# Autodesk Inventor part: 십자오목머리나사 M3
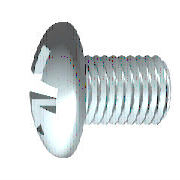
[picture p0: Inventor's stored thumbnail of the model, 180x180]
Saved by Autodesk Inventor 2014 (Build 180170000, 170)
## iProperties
Created: 2012-02
Part Number: 십자오목머리나사 M3
Material: 강철, 연강
Description: 십자 오목 머리 나사
Document SubType Name: Modeling
Standard: KS B 1023
Designer: mduedu
Standards Organization: KS
Language: ko-KR
Size Designation: A  M 3 x 6 - H
Categories: <MemberInstance><Categories><Category DisplayName="조임쇠" InternalName="e4da775c-781d-43d5-af7c-5136215cf5a6" Mnemonic="FSTN"><Category DisplayName="볼트" InternalN
Density: 7.86 g/cm^3
Appearance: 강철
Mass: 0.662382 g
Surface Area: 1.40192 cm^2
Volume: 0.0842726 cm^3
IsCustomPart: 0
Author: mduedu
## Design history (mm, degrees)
body "Solid1"
workplane "Work Plane3"
sketch "스케치2"
  geometry: L1 (-3.72, 0)-(3.72, 0) reference; L2 (0, -3.72)-(0, 3.72) reference; L3 (0, 1.5)-(0, 0); L4 (0, 0)-(1.5, 0); L5 (0, 0)-(1.879, 1.879); L6 (0.253, 1.479)-(0.261, 0.456); L7 (1.479, 0.253)-(0.456, 0.261); L8 (0.253, -1.479)-(0.261, -0.456); L9 (1.479, -0.253)-(0.456, -0.261); L10 (-0.253, 1.479)-(-0.261, 0.456); L11 (-1.479, 0.253)-(-0.456, 0.261); L12 (-1.479, -0.253)-(-0.456, -0.261); L13 (-0.253, -1.479)-(-0.261, -0.456); A1 r 0.45 centre (0, 0) between (0.45, 0) and (0, 0.45); A2 r 1.5 centre (0, 0) between (1.5, 0) and (1.479, 0.253); A3 r 1.5 centre (0, 0) between (0.253, 1.479) and (0, 1.5); A4 r 1.5 centre (0, 0) between (1.479, 0.253) and (0.253, 1.479); A5 r 1.5 centre (0, 0) between (0, -1.5) and (0.253, -1.479); A6 r 1.5 centre (0, 0) between (0.253, -1.479) and (1.479, -0.253); A7 r 1.5 centre (0, 0) between (1.479, -0.253) and (1.5, 0); A8 r 1.5 centre (0, 0) between (-1.479, 0.253) and (-1.5, 0); A9 r 1.5 centre (0, 0) between (-0.253, 1.479) and (-1.479, 0.253); A10 r 1.5 centre (0, 0) between (0, 1.5) and (-0.253, 1.479); A11 r 1.5 centre (0, 0) between (-1.5, 0) and (-1.479, -0.253); A12 r 1.5 centre (0, 0) between (-1.479, -0.253) and (-0.253, -1.479); A13 r 1.5 centre (0, 0) between (-0.253, -1.479) and (0, -1.5); A14 r 0.525 centre (0, 0) between (0.525, 0) and (0, 0.525); A15 r 0.197 centre (0.457, 0.457) between (0.261, 0.456) and (0.456, 0.261); A16 r 0.197 centre (0.457, -0.457) between (0.456, -0.261) and (0.261, -0.456); A17 r 0.197 centre (-0.457, 0.457) between (-0.456, 0.261) and (-0.261, 0.456); A18 r 0.197 centre (-0.457, -0.457) between (-0.261, -0.456) and (-0.456, -0.261); 1 further point
  constraints: 38 point on circle, 22 end point, 19 symmetric about line, 18 centre point, 4 coincident, 3 collinear, 3 point on line, 3 tangent, 1 perpendicular, 21 other
  dimensions: "d4" = 45 deg angle of L5 L4; "d5" = 0.9 diameter of A1 (= 0.3 x SDM); "d6" = 3 diameter of A4 (= SDM); "d7" = 0.2525 distance from line of L6.start L3 (= 0.5 x SBR); "d14" = 1.05 diameter of A14 (= 0.35 x SDM)
extrude "슬롯" join sketch "스케치2" taper "d15" = 5 deg; stored distance "d54" = 10
revolve "절단부" stored, may be unused: angle "d56" = 90 deg
revolve "본체" stored, may be unused: angle "d18" = 90 deg
workplane "Work Plane1"
sketch "스케치1"
  geometry: L1 (6, 0)-(6, 1.5); L2 (6, 1.5)-(1, 1.5); L3 (3.962, 5.08)-(3.962, 5.08); L4 (-2.4, 0)-(-2.4, 2.59); L5 (-2.2, 1.4)-(-1.036, 0.82); L6 (-1.036, 0.82)-(-0.6, 0); L7 (-0.6, 0)-(6, 0); L8 (-4.305, 0)-(7.717, 0) reference; L9 (0, -1.016)-(0, 6.096) reference; L10 (-2.2, 1.4)-(-2.4, 1.5); L11 (-1.636, 2.657)-(-2.4, 2.59); L12 (-1.636, 2.657)-(0, 2.8); L13 (0, 2.8)-(0, 1.347); L14 (0, 1.347)-(0.693, 1.347); L15 (0.693, 1.347)-(1, 1.5); L16 (1, 1.5)-(0, 1.5); A1 r 5 centre (2.6, 0) between (-1.636, 2.657) and (-2.4, 0)
  constraints: 28 end point, 5 point on line, 4 collinear, 4 point on circle, 3 parallel, 2 perpendicular, 1 centre point, 1 horizontal, 1 tangent
  dimensions: "d1" = 3 diameter of L2 L7 (= GD); "d2" = 1.8 distance from line of L6.end L4 (= STI); "d11" = 3 diameter of L10.end L7 (= SDM); "d12" = 62 deg angle of L6 L7; "d13" = 26.5 deg angle of L5 L7; "d17" = 5.6 diameter of L12.end L7 (= KOD); "d19" = 5 deg angle of L12 L7 (= KEWI); "d20" = 2.4 distance between parallel lines of L4 L13 (= KOH); "d21" = 5 radius of A1 (= KR); "d23" = 2.6935 diameter of L14 L7 (= BDM); "d24" = 5 distance of L1.end L2.end (= GEL); "d25" = 0.30673 horizontal distance of L14.end L2.end (= GAL); "d28" = 6 distance between parallel lines of L1 L13 (= NLG)
fillet "모깎기1" dims "d29" = 1.2 (= RR)
fillet "모깎기2" dims "d16" = 0.101 (= 0.2 x SBR)
feature "스레드" dims "d8" = 5 (= GEL), "d9" = 0
chamfer "모따기1" distance "d26" = 0.30673 (= -0.5 x SPD + 0.5 x GD); stored, may be unused: second distance "d27" = 0.30683 (computed from GUL), angle "d78" = 45 deg
other parameters: "GD" = 3 (= NND) [user parameter; used in 2 equation terms], "NLG" = 6 [user parameter; used in 1 equation term], "GEL" = 5 [user parameter; used in 2 equation terms], "KOD" = 5.6 [user parameter; used in 1 equation term], "KOH" = 2.4 [user parameter; used in 2 equation terms], "SDM" = 3 [user parameter; used in 4 equation terms], "STI" = 1.8 [user parameter; used in 1 equation term], "SBR" = 0.505 [user parameter; used in 2 equation terms], "GAL" = 0.30673 (= 0.61345 x PTC) [user parameter; used in 1 equation term], "SPD" = 2.38655 (= NND - 1.2269 x PTC) [user parameter; used in 1 equation term], "KEWI" = 5 deg [user parameter; used in 1 equation term], "d3" = -2.4 (= -KOH), "d10" = 0, "KR" = 5 [user parameter; used in 1 equation term], "BDM" = 2.6935 [user parameter; used in 1 equation term], "GUL" = 0.30673 (= 0.61345 x PTC) [user parameter; used in 1 equation term], "RR" = 1.2 [user parameter; used in 1 equation term], "d79" = 0, "d80" = 0, "PTC" = 0.5 [user parameter; used in 5 equation terms], "THREADDIA" = 3 [user parameter; used in 1 equation term], "TOA" = 30 deg [user parameter], "NND" = 3 [user parameter; used in 2 equation terms], "GD1" = 2.38655 (= THREADDIA - 1.2269 x PTC) [user parameter]
